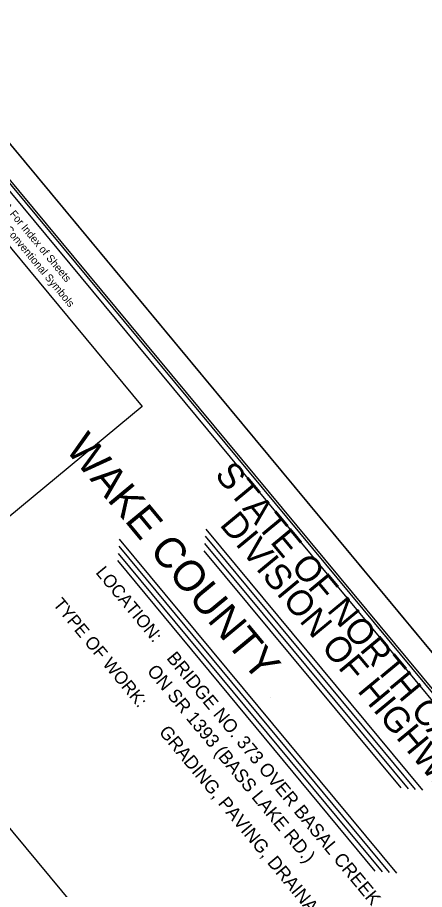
# Model space of a CAD drawing. Extents: x 2054826 to 2060231, y 685508 to 690809.
# Drawn here: x 2058951 to 2059550, y 688824 to 690109 of the extents above; entities that cross this region are included whole.
import ezdxf

# ---------------------------------------------------------------- set-up
doc = ezdxf.new("R2010")
doc.units = 0
for name, color, linetype in [('Default', 7, 'Continuous'), ('Old_Level_21', 7, 'Continuous'), ('Sheet Cutting Line CELL', 7, 'Continuous'), ('Sheet Data Field CELL', 7, 'Continuous'), ('Sheet Plot Border Inside CELL', 7, 'Continuous'), ('Sheet Plot Border Outside CELL', 7, 'Continuous'), ('Sheet Title CELL', 7, 'Continuous'), ('Sheet Title Data Points CELL', 7, 'Continuous')]:
    doc.layers.add(name, color=color, linetype=linetype)

msp = doc.modelspace()

# ---------------------------------------------------------------- linework, layer by layer
at = {"layer": 'Default'}
msp.add_lwpolyline([(2058776.4, 689968), (2059134.7, 689536), (2058721.6, 689193.5), (2058363.3, 689625.5)], close=True, dxfattribs=at)
at = {"layer": 'Old_Level_21'}
msp.add_lwpolyline([(2058588.3, 689338), (2059498.4, 688240.5), (2058988.4, 687817.6), (2058078.3, 688915.1)], close=True, dxfattribs=at)
at = {"layer": 'Sheet Cutting Line CELL'}
msp.add_line((2058618.8, 690310.1), (2060231.3, 688365.7), dxfattribs=at)
at = {"layer": 'Sheet Plot Border Inside CELL'}
msp.add_lwpolyline([(2057387.1, 689263.3), (2058982.8, 687339.1), (2060201, 688349.4), (2058605.4, 690273.6)], close=True, dxfattribs=at)
at = {"layer": 'Sheet Plot Border Outside CELL'}
msp.add_lwpolyline([(2060231.3, 688365.7), (2058618.8, 690310.1), (2057348.7, 689256.9), (2058961.2, 687312.4)], close=True, dxfattribs=at)
at = {"layer": 'Sheet Title CELL'}
for p, q in [((2059228.4, 689355.2), (2059547, 688971)), ((2059101, 689340.5), (2059508.9, 688848.7)), ((2059226.4, 689334.1), (2059525.9, 688973)), ((2059227.4, 689344.7), (2059536.4, 688972)), ((2059100.1, 689330), (2059498.4, 688849.6)), ((2059225.4, 689323.5), (2059515.3, 688974)), ((2059098.1, 689308.9), (2059477.2, 688851.6)), ((2059099.1, 689319.4), (2059487.8, 688850.6))]:
    msp.add_line(p, q, dxfattribs=at)
for points in [[(2060176.5, 688372.9), (2058759.4, 690081.8)], [(2060166, 688373.9), (2058806.3, 690013.5)]]:
    msp.add_lwpolyline(points, dxfattribs=at)
at = {"layer": 'Sheet Title Data Points CELL'}
for p, q in [((2059323.7, 689107.1), (2059323.7, 689107.1)), ((2059375.8, 688916.4), (2059375.8, 688916.4))]:
    msp.add_line(p, q, dxfattribs=at)

# ---------------------------------------------------------------- texts
at = {"layer": 'Sheet Data Field CELL'}
for s, height, p in [('         WAKE COUNTY         ', 45, (2058924.2, 689588.8)), ('BRIDGE NO. 373 OVER BASAL CREEK ', 19.531, (2059169.6, 689164.8)), ('ON SR 1393 (BASS LAKE RD.)', 19.531, (2059140.8, 689145.8)), ('GRADING, PAVING, DRAINAGE, AND STRUCTURE ', 19.531, (2059158.3, 689056))]:
    msp.add_text(s, height=height, rotation=309.6672, dxfattribs=at).set_placement(p)
at = {"layer": 'Sheet Title CELL'}
for s, height, p in [('See Sheet 1-B For Conventional Symbols', 11.25, (2058849.7, 689895.6)), ('See Sheet 1-A For Index of Sheets', 11.25, (2058873.7, 689897.7)), ('STATE OF NORTH CAROLINA', 37.5, (2059240.2, 689434.8)), ('DIVISION OF HIGHWAYS', 37.5, (2059247.6, 689361.3)), ('LOCATION: ', 18.75, (2059065.3, 689291)), ('TYPE OF WORK:', 18.75, (2059002.4, 689244.3))]:
    msp.add_text(s, height=height, rotation=309.6672, dxfattribs=at).set_placement(p)

doc.saveas('drawing.dxf')
